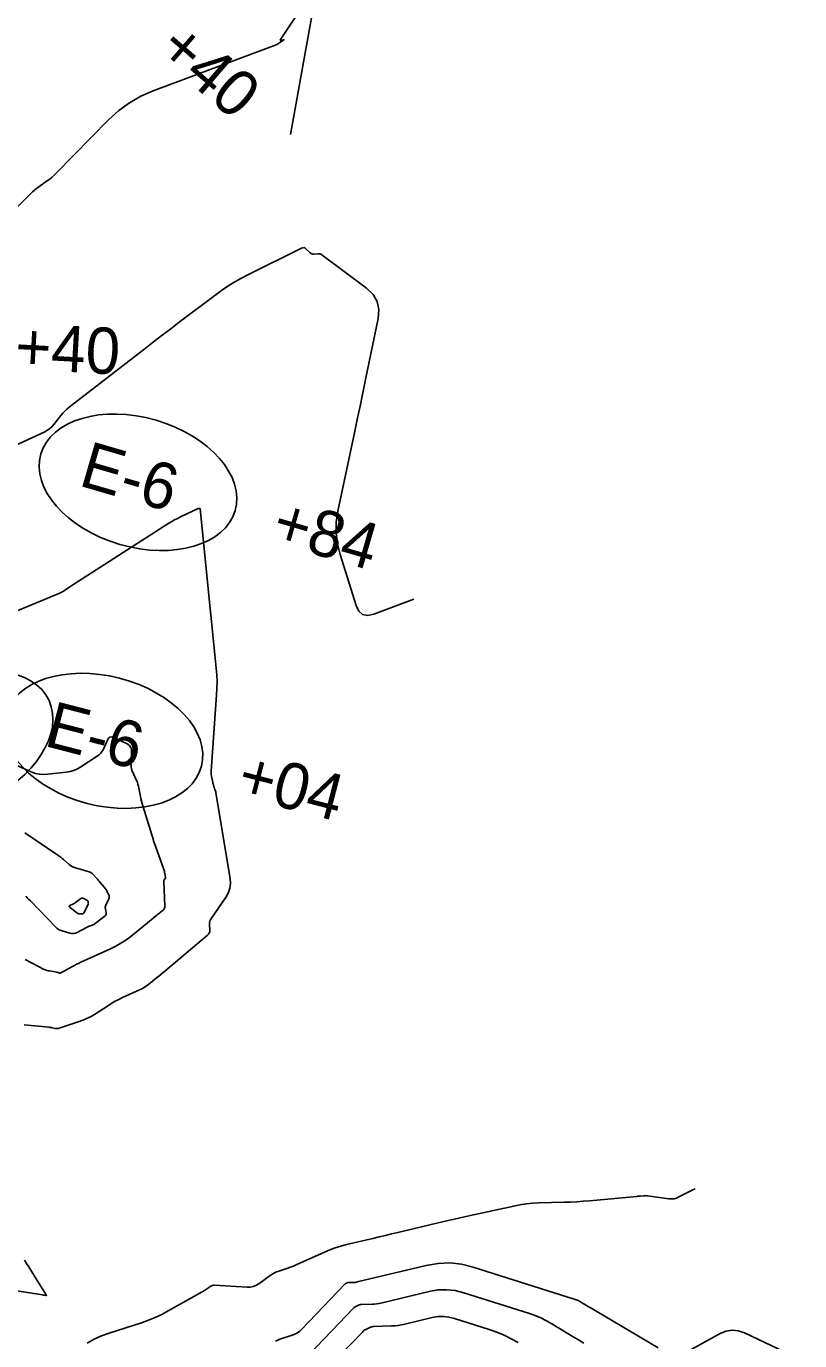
# Model space of a CAD drawing. Extents: x 1005228 to 1008882, y 1883389 to 1885754.
# Drawn here: x 1008190.1 to 1008294.8, y 1884352.9 to 1884530.7 of the extents above; entities that cross this region are included whole.
import ezdxf

# ---------------------------------------------------------------- set-up
doc = ezdxf.new("R2010")
doc.units = 0
for name, color, linetype in [('C-ANNO-NOTE', 7, 'Continuous'), ('R_Erosion', 7, 'Continuous'), ('S_BASELINE', 7, 'Continuous'), ('S_BRIDGE', 7, 'Continuous'), ('TSOBSTACLE', 7, 'Continuous')]:
    doc.layers.add(name, color=color, linetype=linetype)

msp = doc.modelspace()

# ---------------------------------------------------------------- linework, layer by layer
at = {"layer": 'C-ANNO-NOTE'}
for points in [[(1008234.45, 1884543.75), (1008224.53, 1884528.89), (1008224.5, 1884528.83), (1008224.5, 1884528.79), (1008224.54, 1884528.78), (1008224.6, 1884528.78), (1008224.91, 1884528.84), (1008224.97, 1884528.85), (1008225, 1884528.84), (1008224.98, 1884528.82), (1008224.94, 1884528.78), (1008224.19, 1884528.29), (1008224.18, 1884528.29), (1008224.17, 1884528.28), (1008224.16, 1884528.27), (1008224.15, 1884528.27), (1008224.12, 1884528.24), (1008224.11, 1884528.23), (1008224.1, 1884528.23), (1008224.09, 1884528.22), (1008224.08, 1884528.21), (1008224.03, 1884528.17), (1008224.01, 1884528.16), (1008224, 1884528.16), (1008223.99, 1884528.15), (1008223.97, 1884528.14), (1008207.31, 1884521.92), (1008205.65, 1884521.19), (1008204.09, 1884520.3), (1008202.65, 1884519.25), (1008201.31, 1884518.03), (1008194.12, 1884510.72), (1008193.86, 1884510.46), (1008193.59, 1884510.22), (1008193.31, 1884509.99), (1008193.02, 1884509.78), (1008191.83, 1884508.93), (1008191.54, 1884508.71), (1008191.26, 1884508.49), (1008190.99, 1884508.25), (1008190.72, 1884508), (1008184.12, 1884501.46)], [(1008181.26, 1884448.43), (1008194.75, 1884454.02), (1008194.9, 1884454.09), (1008195.05, 1884454.16), (1008195.19, 1884454.25), (1008195.33, 1884454.34), (1008195.88, 1884454.74), (1008196.02, 1884454.83), (1008196.16, 1884454.93), (1008196.3, 1884455.02), (1008196.44, 1884455.11), (1008209.45, 1884463.43), (1008209.83, 1884463.66), (1008210.22, 1884463.88), (1008210.61, 1884464.09), (1008211.01, 1884464.29), (1008213.4, 1884465.42), (1008213.42, 1884465.43), (1008213.44, 1884465.44), (1008213.47, 1884465.44), (1008213.49, 1884465.45), (1008213.6, 1884465.45), (1008213.62, 1884465.44), (1008213.64, 1884465.43), (1008213.65, 1884465.42), (1008213.65, 1884465.4), (1008215.11, 1884451.02), (1008215.21, 1884450.12), (1008215.3, 1884449.23), (1008215.39, 1884448.33), (1008215.48, 1884447.43), (1008215.84, 1884443.84), (1008215.92, 1884442.94), (1008215.95, 1884442.04), (1008215.94, 1884441.14), (1008215.9, 1884440.24), (1008215.16, 1884429.9), (1008215.16, 1884429.73), (1008215.16, 1884429.55), (1008215.18, 1884429.38), (1008215.21, 1884429.22), (1008215.38, 1884428.37), (1008215.4, 1884428.29), (1008215.42, 1884428.2), (1008215.44, 1884428.12), (1008215.47, 1884428.04), (1008215.58, 1884427.65), (1008215.6, 1884427.6), (1008215.62, 1884427.54), (1008215.64, 1884427.48), (1008215.66, 1884427.42), (1008215.75, 1884427.19), (1008215.77, 1884427.13), (1008215.78, 1884427.07), (1008215.8, 1884427.01), (1008215.81, 1884426.95), (1008217.72, 1884415.37), (1008217.77, 1884414.72), (1008217.7, 1884414.09), (1008217.5, 1884413.49), (1008217.19, 1884412.92), (1008215.13, 1884409.89), (1008215.03, 1884409.72), (1008214.97, 1884409.54), (1008214.93, 1884409.36), (1008214.93, 1884409.16), (1008214.97, 1884408.37), (1008214.96, 1884408.18), (1008214.9, 1884408.01), (1008214.81, 1884407.86), (1008214.68, 1884407.72), (1008208.88, 1884402.85), (1008208.61, 1884402.63), (1008208.33, 1884402.4), (1008208.06, 1884402.17), (1008207.78, 1884401.95), (1008206.68, 1884401.05), (1008206.39, 1884400.84), (1008206.1, 1884400.64), (1008205.79, 1884400.46), (1008205.48, 1884400.31), (1008203.15, 1884399.26), (1008202.66, 1884399.02), (1008202.18, 1884398.77), (1008201.71, 1884398.5), (1008201.25, 1884398.21), (1008199.39, 1884397), (1008198.92, 1884396.72), (1008198.44, 1884396.47), (1008197.94, 1884396.25), (1008197.42, 1884396.06), (1008194.46, 1884395.11), (1008194.36, 1884395.09), (1008194.26, 1884395.08), (1008194.16, 1884395.08), (1008194.06, 1884395.1), (1008193.65, 1884395.19), (1008193.54, 1884395.21), (1008193.44, 1884395.23), (1008193.34, 1884395.24), (1008193.23, 1884395.26), (1008189.85, 1884395.6)], [(1008188.37, 1884430.87), (1008190.82, 1884429.8), (1008191.37, 1884429.6), (1008191.93, 1884429.48), (1008192.5, 1884429.44), (1008193.08, 1884429.47), (1008195.52, 1884429.76), (1008196.06, 1884429.85), (1008196.57, 1884430), (1008197.07, 1884430.22), (1008197.54, 1884430.49), (1008199.74, 1884431.92), (1008200, 1884432.12), (1008200.23, 1884432.35), (1008200.42, 1884432.6), (1008200.57, 1884432.89), (1008201.11, 1884434.11), (1008201.27, 1884434.36), (1008201.47, 1884434.49), (1008201.71, 1884434.52), (1008201.99, 1884434.44), (1008203.88, 1884433.56), (1008203.95, 1884433.52), (1008204.01, 1884433.47), (1008204.07, 1884433.42), (1008204.11, 1884433.35), (1008204.28, 1884433.08), (1008204.32, 1884433.01), (1008204.35, 1884432.94), (1008204.36, 1884432.87), (1008204.36, 1884432.79), (1008204.33, 1884430.73), (1008204.34, 1884430.47), (1008204.38, 1884430.22), (1008204.44, 1884429.98), (1008204.54, 1884429.75), (1008204.98, 1884428.82), (1008205.09, 1884428.59), (1008205.17, 1884428.35), (1008205.25, 1884428.1), (1008205.31, 1884427.85), (1008205.59, 1884426.47), (1008205.66, 1884426.16), (1008205.73, 1884425.85), (1008205.82, 1884425.54), (1008205.91, 1884425.23), (1008207.34, 1884420.56), (1008207.37, 1884420.46), (1008207.41, 1884420.33), (1008207.41, 1884420.33), (1008207.41, 1884420.32), (1008207.41, 1884420.32), (1008207.43, 1884420.27), (1008207.43, 1884420.25), (1008207.44, 1884420.24), (1008208.72, 1884416.73), (1008208.76, 1884416.61), (1008208.8, 1884416.48), (1008208.83, 1884416.35), (1008208.85, 1884416.22), (1008208.96, 1884415.55), (1008208.97, 1884415.5), (1008208.96, 1884415.45), (1008208.94, 1884415.4), (1008208.92, 1884415.36), (1008208.8, 1884415.18), (1008208.77, 1884415.13), (1008208.75, 1884415.08), (1008208.74, 1884415.03), (1008208.74, 1884414.98), (1008208.91, 1884411.64), (1008208.9, 1884411.5), (1008208.86, 1884411.38), (1008208.8, 1884411.26), (1008208.7, 1884411.16), (1008208.26, 1884410.79), (1008208.15, 1884410.7), (1008208.04, 1884410.61), (1008207.92, 1884410.51), (1008207.81, 1884410.42), (1008204.27, 1884407.54), (1008203.62, 1884407.05), (1008202.95, 1884406.61), (1008202.26, 1884406.21), (1008201.53, 1884405.85), (1008197.52, 1884404.04), (1008197.23, 1884403.9), (1008196.95, 1884403.77), (1008196.66, 1884403.62), (1008196.39, 1884403.47), (1008194.8, 1884402.6), (1008194.76, 1884402.58), (1008194.72, 1884402.57), (1008194.67, 1884402.57), (1008194.63, 1884402.59), (1008194.45, 1884402.65), (1008194.4, 1884402.67), (1008194.36, 1884402.68), (1008194.31, 1884402.7), (1008194.26, 1884402.7), (1008193.27, 1884402.87), (1008193.09, 1884402.9), (1008192.92, 1884402.95), (1008192.75, 1884403.02), (1008192.58, 1884403.09), (1008189.98, 1884404.42)], [(1008189.93, 1884421.56), (1008194.4, 1884418.55), (1008194.61, 1884418.41), (1008194.81, 1884418.26), (1008195, 1884418.1), (1008195.19, 1884417.94), (1008195.93, 1884417.28), (1008196.12, 1884417.13), (1008196.33, 1884417), (1008196.55, 1884416.9), (1008196.78, 1884416.82), (1008198.63, 1884416.29), (1008198.79, 1884416.23), (1008198.94, 1884416.15), (1008199.07, 1884416.05), (1008199.2, 1884415.93), (1008199.66, 1884415.41), (1008199.77, 1884415.28), (1008199.89, 1884415.14), (1008200, 1884415.01), (1008200.11, 1884414.88), (1008200.73, 1884414.15), (1008200.82, 1884414.04), (1008200.9, 1884413.92), (1008200.98, 1884413.8), (1008201.04, 1884413.67), (1008201.3, 1884413.16), (1008201.34, 1884413.03), (1008201.36, 1884412.9), (1008201.35, 1884412.77), (1008201.3, 1884412.64), (1008200.9, 1884411.76), (1008200.86, 1884411.64), (1008200.83, 1884411.52), (1008200.83, 1884411.39), (1008200.85, 1884411.26), (1008200.95, 1884410.75), (1008200.97, 1884410.62), (1008200.94, 1884410.51), (1008200.89, 1884410.41), (1008200.8, 1884410.33), (1008199.48, 1884409.28), (1008199.39, 1884409.21), (1008199.29, 1884409.16), (1008199.2, 1884409.11), (1008199.09, 1884409.07), (1008198.67, 1884408.92), (1008198.57, 1884408.89), (1008198.47, 1884408.84), (1008198.37, 1884408.8), (1008198.27, 1884408.75), (1008197.03, 1884408.08), (1008196.79, 1884407.97), (1008196.54, 1884407.92), (1008196.29, 1884407.92), (1008196.03, 1884407.97), (1008194.99, 1884408.29), (1008194.74, 1884408.38), (1008194.51, 1884408.5), (1008194.29, 1884408.65), (1008194.09, 1884408.83), (1008190.69, 1884412.35), (1008190.48, 1884412.56), (1008190.28, 1884412.78), (1008190.08, 1884413.01)], [(1008280.66, 1884373.4), (1008280.41, 1884373.31), (1008280.37, 1884373.29), (1008280.33, 1884373.27), (1008280.29, 1884373.25), (1008280.25, 1884373.23), (1008278.44, 1884372.3), (1008278.12, 1884372.16), (1008277.8, 1884372.07), (1008277.46, 1884372.04), (1008277.11, 1884372.06), (1008274.22, 1884372.46), (1008274.1, 1884372.47), (1008273.98, 1884372.48), (1008273.85, 1884372.47), (1008273.73, 1884372.47), (1008273.24, 1884372.42), (1008273.12, 1884372.41), (1008273, 1884372.4), (1008272.88, 1884372.39), (1008272.75, 1884372.37), (1008266.36, 1884371.78), (1008265.5, 1884371.71), (1008264.64, 1884371.65), (1008263.79, 1884371.61), (1008262.93, 1884371.58), (1008259.5, 1884371.49), (1008258.64, 1884371.44), (1008257.79, 1884371.36), (1008256.95, 1884371.24), (1008256.11, 1884371.07), (1008250.64, 1884369.89), (1008249.45, 1884369.62), (1008248.26, 1884369.36), (1008247.07, 1884369.08), (1008245.89, 1884368.8), (1008240.43, 1884367.5), (1008239.58, 1884367.3), (1008238.73, 1884367.1), (1008237.88, 1884366.9), (1008237.03, 1884366.7), (1008233.46, 1884365.86), (1008232.7, 1884365.66), (1008231.95, 1884365.42), (1008231.21, 1884365.15), (1008230.49, 1884364.84), (1008226.76, 1884363.16), (1008226.46, 1884363.03), (1008226.16, 1884362.91), (1008225.85, 1884362.79), (1008225.55, 1884362.69), (1008224.31, 1884362.28), (1008224, 1884362.17), (1008223.71, 1884362.03), (1008223.43, 1884361.87), (1008223.16, 1884361.69), (1008221.59, 1884360.55), (1008221.22, 1884360.33), (1008220.84, 1884360.19), (1008220.44, 1884360.11), (1008220.02, 1884360.1), (1008215.55, 1884360.37), (1008215.43, 1884360.36), (1008215.32, 1884360.34), (1008215.22, 1884360.3), (1008215.12, 1884360.24), (1008214.73, 1884359.96), (1008214.64, 1884359.89), (1008214.54, 1884359.83), (1008214.44, 1884359.77), (1008214.33, 1884359.71), (1008209.35, 1884356.88), (1008208.47, 1884356.42), (1008207.58, 1884355.99), (1008206.66, 1884355.62), (1008205.73, 1884355.29), (1008201.35, 1884353.88), (1008200.33, 1884353.5), (1008199.34, 1884353.05), (1008198.39, 1884352.52)], [(1008223.85, 1884352.81), (1008224.16, 1884352.95), (1008224.47, 1884353.07), (1008226.11, 1884353.6), (1008226.48, 1884353.75), (1008226.82, 1884353.94), (1008227.14, 1884354.16), (1008227.43, 1884354.43), (1008233.26, 1884360.5), (1008233.29, 1884360.53), (1008233.32, 1884360.55), (1008233.36, 1884360.58), (1008233.4, 1884360.6), (1008233.55, 1884360.67), (1008233.59, 1884360.69), (1008233.63, 1884360.7), (1008233.67, 1884360.71), (1008233.71, 1884360.71), (1008234.4, 1884360.73), (1008234.53, 1884360.74), (1008234.65, 1884360.75), (1008234.78, 1884360.77), (1008234.91, 1884360.8), (1008244.27, 1884363.05), (1008245.87, 1884363.32), (1008247.46, 1884363.38), (1008249.04, 1884363.21), (1008250.62, 1884362.82), (1008264.3, 1884358.48), (1008264.55, 1884358.39), (1008264.8, 1884358.29), (1008265.04, 1884358.17), (1008265.27, 1884358.04), (1008266.19, 1884357.48), (1008266.42, 1884357.34), (1008266.65, 1884357.2), (1008266.89, 1884357.06), (1008267.12, 1884356.93), (1008275.66, 1884351.89)], [(1008226.42, 1884348.92), (1008234.44, 1884357.27), (1008234.51, 1884357.33), (1008234.58, 1884357.39), (1008234.66, 1884357.44), (1008234.74, 1884357.49), (1008235.08, 1884357.66), (1008235.17, 1884357.7), (1008235.26, 1884357.73), (1008235.35, 1884357.75), (1008235.44, 1884357.75), (1008236.99, 1884357.79), (1008237.28, 1884357.81), (1008237.56, 1884357.84), (1008237.85, 1884357.88), (1008238.13, 1884357.94), (1008244.66, 1884359.51), (1008245.84, 1884359.72), (1008247.02, 1884359.76), (1008248.19, 1884359.63), (1008249.35, 1884359.35), (1008258.22, 1884356.53), (1008259.02, 1884356.25), (1008259.79, 1884355.93), (1008260.54, 1884355.56), (1008261.27, 1884355.15), (1008264.16, 1884353.4), (1008264.88, 1884352.96), (1008265.6, 1884352.52)], [(1008256.7, 1884352.6), (1008255.76, 1884353.13), (1008254.8, 1884353.61), (1008253.8, 1884354.02), (1008252.78, 1884354.38), (1008248.08, 1884355.87), (1008247.33, 1884356.06), (1008246.58, 1884356.13), (1008245.82, 1884356.11), (1008245.06, 1884355.98), (1008241.35, 1884355.09), (1008240.91, 1884354.99), (1008240.47, 1884354.92), (1008240.03, 1884354.88), (1008239.58, 1884354.85), (1008237.18, 1884354.79), (1008237.03, 1884354.78), (1008236.89, 1884354.75), (1008236.75, 1884354.71), (1008236.62, 1884354.65), (1008236.09, 1884354.38), (1008235.96, 1884354.31), (1008235.84, 1884354.23), (1008235.72, 1884354.14), (1008235.62, 1884354.03), (1008230.91, 1884349.14)], [(1008279.38, 1884351.26), (1008284.02, 1884353.82), (1008284.85, 1884354.16), (1008285.68, 1884354.3), (1008286.51, 1884354.21), (1008287.35, 1884353.92), (1008293.71, 1884350.91)]]:
    msp.add_lwpolyline(points, dxfattribs=at)
msp.add_lwpolyline([(1008197.92, 1884410.7), (1008197.86, 1884410.65), (1008197.78, 1884410.62), (1008197.7, 1884410.61), (1008197.33, 1884410.61), (1008197.24, 1884410.62), (1008197.16, 1884410.64), (1008197.08, 1884410.68), (1008197, 1884410.73), (1008196.02, 1884411.52), (1008195.96, 1884411.58), (1008195.94, 1884411.64), (1008195.97, 1884411.69), (1008196.05, 1884411.74), (1008196.44, 1884411.91), (1008196.54, 1884411.96), (1008196.64, 1884412.01), (1008196.73, 1884412.06), (1008196.82, 1884412.13), (1008197.54, 1884412.66), (1008197.64, 1884412.71), (1008197.73, 1884412.73), (1008197.82, 1884412.72), (1008197.92, 1884412.68), (1008198.43, 1884412.39), (1008198.46, 1884412.36), (1008198.49, 1884412.33), (1008198.5, 1884412.3), (1008198.51, 1884412.26), (1008198.53, 1884412.09), (1008198.54, 1884412.04), (1008198.53, 1884412), (1008198.52, 1884411.96), (1008198.51, 1884411.92), (1008197.96, 1884410.77)], close=True, dxfattribs=at)
at = {"layer": 'R_Erosion'}
msp.add_lwpolyline([(1008518.85, 1884967.78), (1008232.58, 1884553.15), (1008225.88, 1884516.02)], dxfattribs=at)
for centre, major_axis in [((1008205.25, 1884468.97), (13.15, -3.83)), ((1008180.78, 1884433.71), (12.44, 5.73)), ((1008200.58, 1884434), (13.26, -3.43))]:
    msp.add_ellipse(centre, major_axis=major_axis, ratio=0.638788, dxfattribs=at)
at = {"layer": 'S_BRIDGE'}
msp.add_lwpolyline([(1008242.6, 1884453.18), (1008237.17, 1884451.14), (1008236.34, 1884450.96), (1008235.66, 1884451.1), (1008235.14, 1884451.55), (1008234.77, 1884452.31), (1008232.6, 1884459.19), (1008232.24, 1884460.65), (1008232.07, 1884462.12), (1008232.09, 1884463.59), (1008232.31, 1884465.08), (1008234.55, 1884475.68), (1008234.93, 1884477.48), (1008235.31, 1884479.28), (1008235.68, 1884481.07), (1008236.06, 1884482.87), (1008237.76, 1884491.12), (1008237.86, 1884492.33), (1008237.64, 1884493.43), (1008237.08, 1884494.39), (1008236.2, 1884495.24), (1008230.14, 1884499.75), (1008230.02, 1884499.82), (1008229.9, 1884499.87), (1008229.76, 1884499.89), (1008229.62, 1884499.89), (1008229.05, 1884499.84), (1008228.91, 1884499.84), (1008228.78, 1884499.87), (1008228.67, 1884499.92), (1008228.56, 1884500.01), (1008227.98, 1884500.57), (1008227.84, 1884500.67), (1008227.7, 1884500.72), (1008227.55, 1884500.71), (1008227.39, 1884500.66), (1008220.31, 1884497.14), (1008219.09, 1884496.5), (1008217.91, 1884495.81), (1008216.76, 1884495.06), (1008215.64, 1884494.25), (1008210.85, 1884490.63), (1008209.69, 1884489.75), (1008208.53, 1884488.86), (1008207.37, 1884487.97), (1008206.22, 1884487.08), (1008195.95, 1884479.12), (1008195.64, 1884478.87), (1008195.36, 1884478.6), (1008195.09, 1884478.32), (1008194.83, 1884478.02), (1008193.86, 1884476.78), (1008193.6, 1884476.48), (1008193.31, 1884476.23), (1008193, 1884476.01), (1008192.65, 1884475.82), (1008177.66, 1884468.91)], dxfattribs=at)
at = {"layer": 'TSOBSTACLE'}
msp.add_lwpolyline([(1008189.91, 1884363.77), (1008190.19, 1884363.32), (1008190.47, 1884362.87), (1008190.75, 1884362.41), (1008191.03, 1884361.96), (1008192.84, 1884359.05), (1008192.86, 1884359.01), (1008192.86, 1884358.98), (1008192.83, 1884358.97), (1008192.79, 1884358.97), (1008192.56, 1884359.01), (1008192.5, 1884359.02), (1008192.45, 1884359.03), (1008192.39, 1884359.03), (1008192.34, 1884359.04), (1008185.68, 1884360.09)], dxfattribs=at)

# ---------------------------------------------------------------- texts
at = {"layer": 'R_Erosion'}
for rotation, p in [(343.7587, (1008197.06, 1884468.58)), (345.5081, (1008192.4, 1884433.36))]:
    msp.add_text('E-6', height=6.25, rotation=rotation, dxfattribs=at).set_placement(p)
at = {"layer": 'S_BASELINE'}
for s, rotation, p in [('+40', 319.3502, (1008207.54, 1884527.02)), ('+40', 356.8594, (1008188.51, 1884484.31)), ('+84', 343.7587, (1008223.05, 1884461.01)), ('+04', 345.5081, (1008218.38, 1884426.65))]:
    msp.add_text(s, height=6.25, rotation=rotation, dxfattribs=at).set_placement(p)

doc.saveas('drawing.dxf')
